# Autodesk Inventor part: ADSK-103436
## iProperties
Shininess: 0.0
Created: 2000-11
Part Number: ADSK-103436
Description: MFC - 28    SEALMASTER
Document SubType Name: Modeling
Stock Number: ADSK-103436
Density: 1 g/cm^3
Density: 0.0
Volumn: 0.0
Area: 0.0
PropertySet Name: Model Information
Control State: 0
Master: False
Checked Out: False
Author: gao
